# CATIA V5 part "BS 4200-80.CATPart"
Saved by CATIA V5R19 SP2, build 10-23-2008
Part number: BS 4200-80
Bounding box of the stored display mesh (mm): x -47.487 to 47.487, y -47.487 to 47.487, z 0 to 225
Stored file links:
  C:\Users\Bora\Desktop\3D Katı model\BS serisi\BS 4200\BS 4200-80.CATPart
  C:\Program Files\Dassault Systemes\B19\intel_a\reffiles\standard\MetricThickPitch.txt
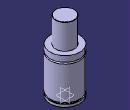
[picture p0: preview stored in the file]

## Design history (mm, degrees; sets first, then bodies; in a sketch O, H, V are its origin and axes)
Body1 (main body)
  Sketch1 on yz-plane, origin (0, 0, 0), H (0, 1, 0), V (0, 0, 1)
    point P2 (47.5, 120.5)
    point P5 (30, 224)
    point P7 (30, 224)
    point P11 (47.5, 125.5)
    point P13 (47.5, 125.5)
    point P14 (47.5, 120.5)
    line L1 (47.5, 13) -> (47.5, 120.5)
    line L2 (44.5, 13) -> (44.5, 8)
    line L3 (30, 224) -> (30, 144)
    arc A1 centre (29, 224) radius 1 from (30, 224) to (29, 225) ccw
    line L4 (47.5, 0) -> (47.5, 8)
    line L5 (47.5, 125.5) -> (47.5, 144)
    arc A2 centre (47.5, 123) radius 2.5 from (47.5, 125.5) to (47.5, 120.5) ccw
    line L6 (29, 225) -> (0, 225)
    point P15 (0, 225)
    line L7 (30, 144) -> (47.5, 144)
    line L8 (0, 0) -> (47.5, 0)
    line L9 (44.5, 13) -> (47.5, 13)
    line L10 (44.5, 8) -> (47.5, 8)
    coincidence: P15 V, P2 P14, P5 P7, P11 P13
    tangency: L6 A1
    horizontal: L7 H, L8 H, L9 H, L10 H
  Shaft1: profile Sketch1, axis Sketch1.V, angle 360
  Sketch2 on face of Shaft1 from Sketch1.L8, origin (0, 0, 0), H (1, 0, 0), V (0, -1, 0)
    point P1 (30, 0)
    distance P1 V = 30
  Hole1: placed by Sketch2, at (30, 0, 0) direction (0, 0, 1), diameter 6.647, depth 7, threaded "M8", thread diameter 8, thread depth 7, pitch 1.25
  CircPattern1: of Hole1, instances 4, angular step 90, axis from xy-plane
